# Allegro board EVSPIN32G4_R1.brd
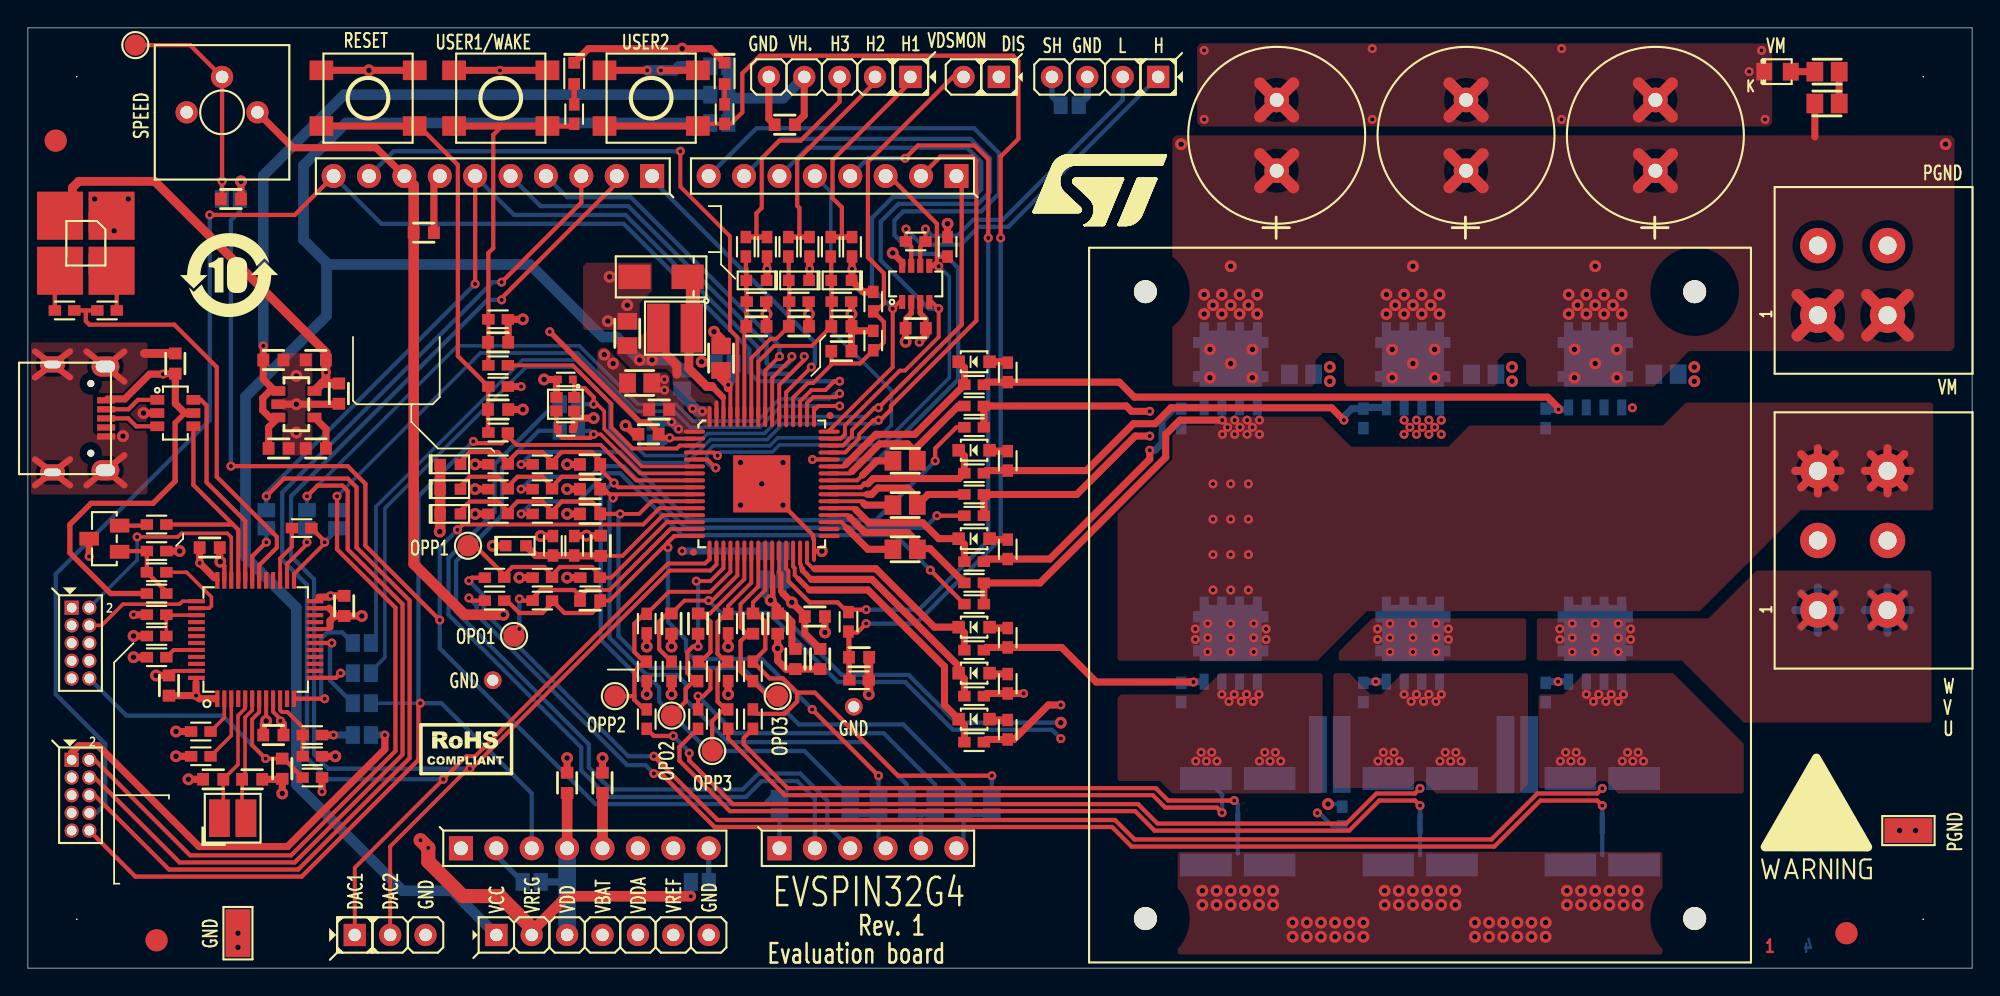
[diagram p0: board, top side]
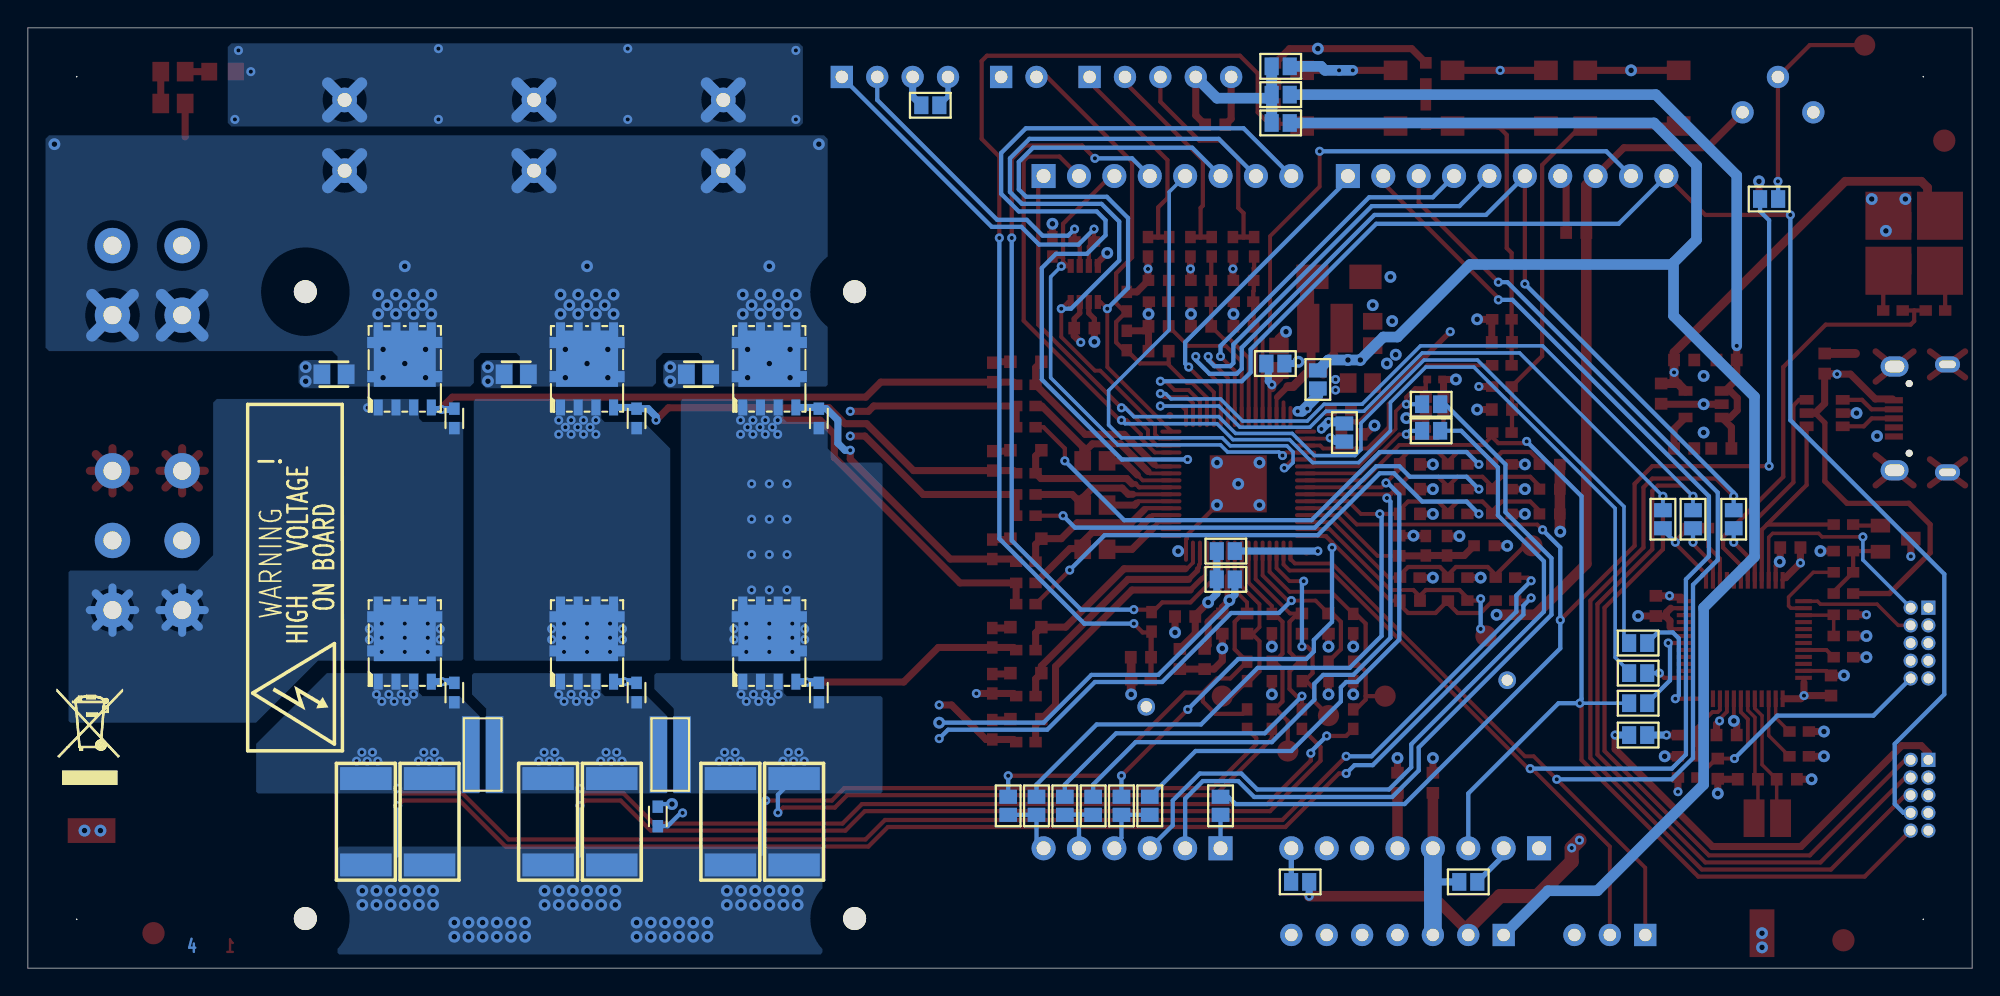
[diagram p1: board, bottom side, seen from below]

Outline 139.54 x 67.5 mm; copper layers: TOP, GND, PWR, BOTTOM. Coordinates in mm from the lower left corner of the outline.
Outline path: 0,67.5 0,0 139.54,0 139.54,67.5 0,67.5

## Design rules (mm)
constraint set DEFAULT: min track width 0.2
net group VSHUNT1: nets VSHUNT1N
net group VSHUNT2: nets VSHUNT2N
net group VSHUNT3: nets VSHUNT3N

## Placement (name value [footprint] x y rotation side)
C1  10uF  [C0805]  43.02 45.56 270 top
C2  220nF  [C0805]  49.75 43.78 270 top
C3  C-0603  [C0603]  58.39 44.29 180 top
C4  6.8pF  [C0402]  38.57 42.26 180 top
C5  6.8pF  [C0402]  38.57 38.7 180 top
C6  10uF  [C0805]  43.91 42 0 top
C7  100nF  [C0603]  45.31 40.1 180 top
C8  1uF  [C0603]  56.86 22.19 90 top
C9  100nF  [C0603]  56.48 25.24 0 top
C10  1uF  [C0603]  53.81 24.73 90 top
C11  100nF  [C0603]  55.08 22.19 270 top
C12  100nF  [C0603]  44.54 38.32 180 top
C13  220nF  [C0805]  117.57 42.64 180 bottom
C14  220nF  [C0805]  104.49 42.64 180 bottom
C15  220nF  [C0805]  91.41 42.64 180 bottom
C16  1uF  [C0805]  62.96 36.42 180 top
C17  1uF  [C0805]  62.96 33.24 180 top
C18  1uF  [C0805]  62.96 30.07 180 top
C19  33nF  [C0603]  41.11 30.32 270 top
C20  33nF  [C0603]  46.19 24.73 90 top
C21  33nF  [C0603]  14.57 55.21 180 top
C22  C-0603  [C0603]  40.35 26.38 180 top
C23  C-0603  [C0603]  48.1 24.73 270 top
C24  C-0603  [C0603]  52.04 24.73 270 top
C25  82nF  [C0603]  40.35 36.16 0 top
C26  82nF  [C0603]  40.35 34.38 0 top
C27  82nF  [C0603]  40.35 32.61 0 top
C28  100nF  [C0603]  38.7 13.3 90 top
C29  100nF  [C0603]  41.24 13.3 90 top
C30  100nF  [C0603]  28.41 52.8 0 top
C31  220uF  [D500P200]  89.63 59.78 90 top
C32  220uF  [D500P200]  103.22 59.78 90 top
C33  220uF  [D500P200]  116.81 59.78 90 top
C34  1nF  [C0603]  58.39 46.07 0 top
C35  1nF  [C0603]  55.34 46.07 0 top
C36  1nF  [C0603]  52.29 46.07 0 top
C37  100nF  [C0603]  54.32 60.55 0 top
C38  1nF  [C0603]  33.75 44.93 0 top
C39  1nF  [C0603]  59.66 22.32 0 top
C40  1nF  [C0603]  33.75 40.1 0 top
C41  100nF  [C0603]  63.72 45.94 180 top
C42  100nF  [C0603]  10.58 43.4 270 top
C43  100nF  [C0603]  20.67 43.66 0 top
C44  1uF  [C0603]  17.62 43.66 180 top
C45  100nF  [C0603]  18 37.31 180 top
C46  1uF  [C0603]  22.32 41.24 90 top
C47  10nF  [C0603]  20.67 37.31 0 top
C48  100pF  [C0603]  13.3 13.56 180 top
C49  100pF  [C0603]  16.1 13.56 0 top
C50  100nF  [C0603]  18.25 14.32 90 top
C51  100nF  [C0603]  10.13 20.29 270 top
C52  100nF  [C0603]  17.62 16.73 0 top
C53  100nF  [C0603]  22.7 26 90 top
C54  100nF  [C0603]  13.05 30.19 180 top
CN5  STRIP-P2_54-10P-FEMALE  [SIL-SOCKET10PIN-P254]  33.37 56.86 270 top
CN6  STRIP-P2_54-8P-FEMALE  [SIL-SOCKET8PIN-P254]  39.97 8.6 90 top
CN8  STRIP-P2_54-6P-FEMALE  [SIL-SOCKET6PIN-P254]  60.29 8.6 0 top
CN9  STRIP-P2_54-8P-FEMALE  [SIL-SOCKET8PIN-P254]  57.75 56.86 270 top
CON1  Power con3P  [2834082-2-TE]  130.97 30.7 90 top
CON2  Power con2P  [2834082-1-TE]  130.97 49.37 90 top
D1  STPS1H100A  [SMA]  45.45 49.62 270 top
D2  BAT60J  [SOD-323]  67.91 43.53 0 top
D3  BAT60J  [SOD-323]  67.91 37.18 0 top
D4  BAT60J  [SOD-323]  67.91 30.83 0 top
D5  BAT60J  [SOD-323]  67.91 17.87 0 top
D6  BAT60J  [SOD-323]  67.91 21.18 0 top
D7  BAT60J  [SOD-323]  67.91 24.48 0 top
D8  BAT30K  [SOD523]  35.02 30.32 0 top
D9  BAT30K  [SOD523]  30.32 36.16 0 top
D10  BAT30K  [SOD523]  30.32 34.38 0 top
D11  BAT30K  [SOD523]  30.32 32.61 0 top
D12  BAT30K  [SOD523]  58.39 49.37 180 top
D13  BAT30K  [SOD523]  55.34 49.37 180 top
D14  BAT30K  [SOD523]  52.29 49.37 180 top
J2  STRIP 1x2  [STRIP254P-M-2]  68.42 63.98 270 top
J3  STRIP 2x5  [PIN2X5P127]  3.78 12.41 0 top
J4  STRIP 1x3  [STRIP254P-M-3]  26 2.38 90 top
J5  STRIP 1x7  [STRIP254P-M-7]  41.24 2.38 90 top
J6  STRIP 1x5  [STRIP254P-M-5]  58.26 63.98 270 top
J7  STRIP 1x4  [STRIP254P-M-4]  77.31 63.98 270 top
J8  Micro USB Type B  [629105150521-USB-MICRO-B-WE]  -0.03 39.46 270 top
J9  STRIP 2x5  [PIN2X5P127]  3.78 23.34 0 top
JP1  OPEN  [JUMPER-LARGO5_5MM]  106.9 15.33 90 bottom
JP2  OPEN  [JUMPER-LARGO5_5MM]  93.44 15.33 90 bottom
L1  18uH  [7447732115-WURTH]  46.45 45.94 180 top
LED1  RED  [LED-0805]  125.57 64.36 0 top
LED2  YELLOW  [LED-0603]  39.21 64.23 270 top
LED3  YELLOW  [LED-0603]  50 64.23 270 top
LED4  RED-GREEN LED  [PLCC4]  4.16 52.04 180 top
NET1  PCB short  [CURRENTSENSE]  113 10.38 270 bottom
NET2  PCB short  [CURRENTSENSE]  99.92 10.38 270 bottom
NET3  PCB short  [CURRENTSENSE]  86.83 10.38 270 bottom
NOREF  -  [unnamed]  2 59.4 0 top
NOREF#2  -  [#2]  139.54 0 90 top
NOREF#3  -  [#2]  72.09 53.69 0 top
NOREF#4  -  [unnamed#3]  99.92 26.06 0 top
NOREF#5  -  [unnamed]  9.24 2 0 top
NOREF#6  -  [unnamed]  136.04 64 90 top
NOREF#7  -  [#2]  10.92 46.74 0 top
NOREF#8  -  [unnamed]  3.5 3.5 90 top
NOREF#9  -  [#2]  128.17 9.01 0 top
NOREF#10  -  [unnamed]  130.52 2.51 0 top
NOREF#11  -  [unnamed]  3.5 64 90 top
NOREF#12  -  [#2]  0 67.5 0 top
NOREF#13  -  [#2]  219.42 15.46 0 top
NOREF#14  -  [#2]  31.39 15.71 0 top
NOREF#15  -  [unnamed]  136.04 3.5 90 top
NOREF#16  -  [#2]  5.55 -99.73 0 top
NOREF#17  -  [#2]  134.59 43.66 0 top
NOREF#18  -  [#2]  120.13 27.84 90 bottom
NOREF#19  -  [#2]  135.14 17.46 180 bottom
NTC1  10k  [R0603]  94.33 10.89 180 bottom
Q1  STL110N10F7  [PFLAT_6X5-8LEADS]  112.49 43.02 90 bottom
Q2  STL110N10F7  [PFLAT_6X5-8LEADS]  99.41 43.02 90 bottom
Q3  STL110N10F7  [PFLAT_6X5-8LEADS]  86.33 43.02 90 bottom
Q4  STL110N10F7  [PFLAT_6X5-8LEADS]  112.49 23.34 90 bottom
Q5  STL110N10F7  [PFLAT_6X5-8LEADS]  99.41 23.34 90 bottom
Q6  STL110N10F7  [PFLAT_6X5-8LEADS]  86.33 23.34 90 bottom
Q7  BC847B  [SOT23]  5.49 30.83 90 top
R1  0  [J0805]  50 43.4 270 bottom
R2  22k  [R0603]  60.67 47.85 180 top
R3  10k  [R0603]  60.67 45.05 0 top
R6  0  [J0805]  46.96 42.26 0 bottom
R7  0  [J0805]  45.05 38.45 0 bottom
R8  0  [J0805]  53.56 29.94 90 bottom
R9  0  [J0805]  53.56 27.91 270 bottom
R10  0  [R0603]  70.32 42.77 0 top
R11  0  [R0603]  70.32 36.42 0 top
R12  0  [R0603]  70.32 30.07 0 top
R13  33  [R0603]  67.91 41.88 90 top
R14  33  [R0603]  67.91 35.53 90 top
R15  33  [R0603]  67.91 29.18 90 top
R16  R-0805  [R0603]  108.93 39.46 0 bottom
R17  R-0805  [R0603]  95.85 39.46 0 bottom
R18  R-0805  [R0603]  82.77 39.46 0 bottom
R19  0  [R0603]  67.91 40.35 90 top
R20  0  [R0603]  67.91 34 90 top
R21  0  [R0603]  67.91 27.65 90 top
R22  0  [R0603]  70.32 17.11 0 top
R23  0  [R0603]  70.32 20.41 0 top
R24  0  [R0603]  70.32 23.72 0 top
R25  33  [R0603]  67.91 16.22 90 top
R26  33  [R0603]  67.91 19.53 90 top
R27  33  [R0603]  67.91 22.83 90 top
R28  R-0805  [R0603]  108.93 19.78 0 bottom
R29  R-0805  [R0603]  95.85 19.78 0 bottom
R30  R-0805  [R0603]  82.77 19.78 0 bottom
R31  10m  [R2512]  110.71 10.51 90 bottom
R32  10m  [R2512]  115.28 10.51 90 bottom
R33  10m  [R2512]  97.63 10.51 90 bottom
R34  10m  [R2512]  102.2 10.51 90 bottom
R35  10m  [R2512]  84.55 10.51 90 bottom
R36  10m  [R2512]  89.12 10.51 90 bottom
R37  72.3k  [R0603]  37.69 30.32 180 top
R38  0  [J0805]  14.57 55.21 90 bottom
R39  3.01k  [R0603]  39.21 30.32 0 top
R40  4.7k  [R0603]  46.19 21.3 180 top
R41  22k  [R0603]  36.92 28.03 270 top
R42  22k  [R0603]  44.42 21.3 0 top
R43  22k  [R0603]  50.26 21.3 0 top
R44  1.5k  [R0603]  33.49 28.03 90 top
R45  1.5k  [R0603]  44.42 17.87 180 top
R46  1.5k  [R0603]  50.26 17.87 180 top
R47  22k  [R0603]  40.35 28.03 90 top
R48  22k  [R0603]  44.42 24.73 180 top
R49  22k  [R0603]  50.26 24.73 180 top
R50  1.5k  [R0603]  33.49 26.38 90 top
R51  1.5k  [R0603]  48.1 17.87 180 top
R52  1.5k  [R0603]  52.04 17.87 180 top
R53  11k  [R0603]  36.92 26.38 90 top
R54  11k  [R0603]  48.1 21.3 180 top
R55  11k  [R0603]  52.04 21.3 180 top
R56  68k  [R0603]  67.91 38.83 270 top
R57  27k  [R0603]  36.92 36.16 90 top
R58  68k  [R0603]  67.91 32.48 270 top
R59  27k  [R0603]  36.92 34.38 90 top
R60  68k  [R0603]  67.91 26.13 270 top
R61  27k  [R0603]  36.92 32.61 90 top
R62  3.9k  [R0603]  33.75 36.16 90 top
R63  3.9k  [R0603]  33.75 34.38 90 top
R64  3.9k  [R0603]  33.75 32.61 90 top
R65  0  [J0805]  36.16 6.19 270 bottom
R66  0  [J0805]  48.23 6.19 270 bottom
R67  0  [J0805]  53.94 11.65 0 bottom
R68  0  [J0805]  38.83 40.48 270 bottom
R69  0  [J0805]  38.83 38.58 270 bottom
R70  0  [J0805]  59.02 11.65 0 bottom
R71  0  [J0805]  63.09 11.65 0 bottom
R72  0  [J0805]  67.15 11.65 0 bottom
R73  0  [J0805]  61.05 11.65 0 bottom
R74  0  [J0805]  65.12 11.65 0 bottom
R75  0  [J0805]  69.18 11.65 0 bottom
R76  4.7k  [R0805]  129.13 62.07 0 top
R77  4.7k  [R0805]  129.13 64.36 180 top
R78  10k  [R0603]  59.15 51.78 180 top
R79  10k  [R0603]  56.1 51.78 180 top
R80  10k  [R0603]  53.05 51.78 180 top
R81  10k  [R0603]  57.62 51.78 0 top
R82  10k  [R0603]  54.58 51.78 0 top
R83  10k  [R0603]  51.53 51.78 0 top
R84  0  [J0805]  49.62 62.71 90 bottom
R85  R-0603  [R0603]  58.39 47.85 270 top
R86  R-0603  [R0603]  55.34 47.85 270 top
R87  0  [J0805]  49.62 60.67 90 bottom
R88  R-0603  [R0603]  52.29 47.85 270 top
R89  0  [J0805]  49.62 64.74 90 bottom
R90  100k  [R0603]  33.75 41.75 90 top
R91  200  [R0603]  33.75 43.27 90 top
R92  200  [R0603]  33.75 38.45 90 top
R93  100k  [R0603]  33.75 46.58 90 top
R94  120  [R0603]  39.21 61.31 180 top
R95  120  [R0603]  50 61.31 180 top
R96  200  [R0603]  58.89 24.86 180 top
R97  100k  [R0603]  59.66 20.67 90 top
R98  120  [R0603]  63.72 52.16 270 top
R99  10k  [R0603]  66.01 51.78 0 top
R100  0  [J0805]  74.77 61.94 90 bottom
R101  10k  [R0603]  9.24 26.89 270 top
R102  100  [R0603]  9.24 28.42 90 top
R103  36k  [R0603]  9.24 29.94 270 top
R104  1.5k  [R0603]  9.24 31.84 270 top
R105  4.7k  [R0603]  20.41 16.73 90 top
R106  4.7k  [R0603]  20.41 15.21 270 top
R107  4.7k  [R0603]  9.24 23.84 90 top
R108  0  [J0805]  23.97 16.73 90 bottom
R109  0  [J0805]  23.97 23.34 90 bottom
R110  2.7k  [R0603]  9.24 25.37 270 top
R111  0  [J0805]  23.97 21.18 90 bottom
R112  0  [J0805]  20.03 32.23 180 bottom
R113  0  [J0805]  22.19 32.23 180 bottom
R114  100  [R0603]  19.65 31.59 90 top
R115  0  [J0805]  17.11 32.23 180 bottom
R116  10k  [R0603]  12.41 16.99 270 top
R117  R-0603  [R0603]  12.41 15.21 270 top
R118  0  [J0805]  23.97 19.02 90 bottom
R119  100k  [R0603]  9.24 22.32 90 top
R120  100k  [R0603]  20.41 13.68 90 top
R121  100  [R0603]  2.63 47.21 270 top
R122  100  [R0603]  5.68 47.21 90 top
SW1  6x6 J-bend SMT  [BUTTON_L6_2_W6_2]  33.94 62.45 180 top
SW2  6x6 J-bend SMT  [BUTTON_L6_2_W6_2]  44.73 62.45 180 top
SW3  6x6 J-bend SMT  [BUTTON_L6_2_W6_2]  24.41 62.45 180 top
TP1  TP-SMD-S1751-46R  [TP_SMD_135_70]  134.97 9.87 0 top
TP2  TP-SMD-S1751-46R  [TP_SMD_135_70]  15.08 2.51 90 top
TP3  TP-SMD-diam1_5mm  [TP-D60]  7.71 66.26 90 top
TP4  TP-SMD-diam1_5mm  [TP-D60]  31.59 30.32 270 top
TP5  TP-SMD-diam1_5mm  [TP-D60]  42.13 19.53 270 top
TP6  TP-SMD-diam1_5mm  [TP-D60]  49.12 15.59 270 top
TP7  TP-SMD-diam1_5mm  [TP-D60]  34.89 23.84 270 top
TP8  TP-SMD-diam1_5mm  [TP-D60]  46.19 18.13 90 top
TP9  TP-SMD-diam1_5mm  [TP-D60]  53.81 19.53 90 top
TP10  TP-diam1_27mm-Hole0_8mm  [TP-SONDA]  59.28 18.76 0 top
TP11  TP-diam1_27mm-Hole0_8mm  [TP-SONDA]  33.37 20.67 0 top
TR1  100k  [TRIMMER-3386P-BOURNS]  13.94 61.44 0 top
U1  STSPIN32G4  [VFQFPN9X9X1_0-64L-EXP]  52.67 34.77 0 top
U2  TCAN330DCNT  [SOT23-8L]  63.72 49.12 0 top
U3  LD3985M33R  [SOT23-5L]  19.27 40.48 270 top
U4  USBLC6-2SC6  [SOT23-6L]  10.58 39.85 270 top
U5  STM32F103CBT6  [LQFP48_L7_W7_P0_5]  16.35 23.59 90 top
X1  24.000MHZ  [ABMM11W]  38.57 40.48 180 top
X2  NX3225CD-CRYSTAL  [XTAL_L3_2_W2_5_2PINS]  14.7 10.76 0 top

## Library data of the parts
C1 C2 C6 C13-C18 = C-0805
C3 C7-C12 C19-C30 C34-C54 = C-0603
C4 C5 = C-0402
C31-C33 = CAP POL: Tolerance: TOL; User Part Number: PART#
CN5 = STRIP-P2_54-10P-FEMALE
CN6 CN9 = STRIP-P2_54-8P-FEMALE
CN8 = STRIP-P2_54-6P-FEMALE
CON1 = TE_con3P_20A_p5mm
CON2 = TE_con2P_20A_p5mm
D1 = STPS1H100A
D2-D7 = BAT60J
D8-D14 = BAT30K
J2 = STRIP 1x2
J3 J9 = STRIP 2x5
J4 = STRIP 1x3
J5 = STRIP 1x7
J6 = STRIP 1x5
J7 = STRIP 1x4
J8 = USB-microB-629105150521-WE-SMT
JP1 JP2 = Jumper a Goccia-Largo 5_5mm
L1 = INDUCTOR-7447732115-WE
LED1 = LED-0805-RED-WE
LED2 LED3 = LED-0603-YELLOW-WE
LED4 = HSMF-A201-A00J1
NET1-NET3 = CurrentSense
NTC1 = NTC-NCP18XH103F03RB
Q1-Q6 = STLD110N10F7
Q7 = BC847B
R1-R3 R6-R9 R37-R122 = R-0603
R10-R30 = R-0805
R31-R36 = R-2512
SW1-SW3 = 430483025816
TP1 TP2 = TP-SMD-S2761-46R
TP3-TP9 = TP-SMD-diam1_5mm
TP10 TP11 = TP-diam1_27mm-Hole0_8mm
TR1 = TRIMMER 3386P
U1 = STSPIN32G4
U2 = TCAN330DCNT
U3 = LD3985M33R
U4 = USBLC6-2SC6
U5 = STM32F103CBT6
X1 = CRYSTAL-ABM11W
X2 = NX3225CD-CRYSTAL

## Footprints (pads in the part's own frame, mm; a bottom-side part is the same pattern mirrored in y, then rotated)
2834082-1-TE
  round 2.54 hole 1.3: 1(-2.5,2.5) 2(-2.5,-2.5) 3(2.5,2.5) 4(2.5,-2.5)
2834082-2-TE
  round 2.54 hole 1.3: 1(-5,2.5) 2(-5,-2.5) 3(0,2.5) 4(0,-2.5) 5(5,2.5) 6(5,-2.5)
7447732115-WURTH
  rect 1.6x3.5 smd: 1(-1.2,0) 2(1.2,0)
629105150521-USB-MICRO-B-WE
  round 0.508 hole 0.8 unplated: (-2.5,4.55) (2.5,4.55)
  rect 0.45x1.3 smd: 1(-1.3,5.65) 2(-0.65,5.65) 3(0,5.65) 4(0.65,5.65) 5(1.3,5.65)
  oval 1.45x2 hole 0.85x1.4: SH1(-3.725,5.6) SH2(3.725,5.6)
  oval 1.15x1.8 hole 0.55x1.2: SH3(-3.875,1.8) SH4(3.875,1.8)
ABMM11W
  rect 0.875x0.775 smd: 1(-0.638,-0.487) 2(0.638,-0.487) 3(0.638,0.487) 4(-0.638,0.487)
BUTTON_L6_2_W6_2
  rect 1.7x1.4 smd: 1(-3.35,1.999) 2(3.35,1.999) 3(-3.35,-1.999) 4(3.35,-1.999)
C0402
  rect 0.559x0.559 smd: 1(-0.533,0) 2(0.533,0)
C0603
  rect 0.85x0.9 smd: 1(-0.725,0) 2(0.725,0)
C0805
  rect 1.2x1.4 smd: 1(-0.875,0) 2(0.875,0)
CURRENTSENSE
  rect 0.762x0.381 smd: 1(-0.356,0) 2(0.356,0)
D500P200
  round 1.778 hole 1: 1(-2.54,0) 2(2.54,0)
J0805
  rect 1.27x1.016 smd: 1(0,0.648) 2(0,-0.648)
JUMPER-LARGO5_5MM
  rect 5.5x1.27 smd: 1(0,0.851) 2(0,-0.851)
LED-0603
  rect 0.838x0.838 smd: 1(-0.762,0) 2(0.762,0)
LED-0805
  rect 1.143x1.27 smd: 1(-0.953,0) 2(0.953,0)
LQFP48_L7_W7_P0_5
  rect 1.2x0.3 smd: 1(-4.25,2.75) 2(-4.25,2.25) 3(-4.25,1.75) 4(-4.25,1.25) 5(-4.25,0.75) 6(-4.25,0.25) 7(-4.25,-0.25) 8(-4.25,-0.75) 9(-4.25,-1.25) 10(-4.25,-1.75) 11(-4.25,-2.25) 12(-4.25,-2.75) 25(4.25,-2.75) 26(4.25,-2.25) 27(4.25,-1.75) 28(4.25,-1.25) 29(4.25,-0.75) 30(4.25,-0.25) 31(4.25,0.25) 32(4.25,0.75) 33(4.25,1.25) 34(4.25,1.75) 35(4.25,2.25) 36(4.25,2.75)
  rect 0.3x1.2 smd: 13(-2.75,-4.25) 14(-2.25,-4.25) 15(-1.75,-4.25) 16(-1.25,-4.25) 17(-0.75,-4.25) 18(-0.25,-4.25) 19(0.25,-4.25) 20(0.75,-4.25) 21(1.25,-4.25) 22(1.75,-4.25) 23(2.25,-4.25) 24(2.75,-4.25) 37(2.75,4.25) 38(2.25,4.25) 39(1.75,4.25) 40(1.25,4.25) 41(0.75,4.25) 42(0.25,4.25) 43(-0.25,4.25) 44(-0.75,4.25) 45(-1.25,4.25) 46(-1.75,4.25) 47(-2.25,4.25) 48(-2.75,4.25)
PFLAT_6X5-8LEADS
  rect 1.143x0.65 smd: 1(-2.771,1.905) 2(-2.771,0.635) 3(-2.771,-0.635) 4(-2.771,-1.905) 5(2.771,-1.905) 6(2.771,-0.635) 7(2.771,0.635) 8(2.771,1.905)
PIN2X5P127
  rect 1.016x1.016 hole 0.7: 1(-0.635,2.54)
  round 1.016 hole 0.7: 2(0.635,2.54) 3(-0.635,1.27) 4(0.635,1.27) 5(-0.635,0) 6(0.635,0) 7(-0.635,-1.27) 8(0.635,-1.27) 9(-0.635,-2.54) 10(0.635,-2.54)
PLCC4
  rect 1.1x1.5 smd: A1(-0.75,1.5) A2(0.75,-1.5) K1(-0.75,-1.5) K2(0.75,1.5)
R0603
  rect 0.762x0.889 smd: 1(0,0.699) 2(0,-0.699)
R0805
  rect 1.2x1.4 smd: 1(-0.875,0) 2(0.875,0)
R2512
  rect 1.65x3.7 smd: 1(-3.1,0) 2(3.1,0)
SIL-SOCKET6PIN-P254
  rect 1.727x1.727 hole 1: 1(-6.35,0)
  round 1.727 hole 1: 2(-3.81,0) 3(-1.27,0) 4(1.27,0) 5(3.81,0) 6(6.35,0)
SIL-SOCKET8PIN-P254
  rect 1.727x1.727 hole 1: 1(0,8.89)
  round 1.727 hole 1: 2(0,6.35) 3(0,3.81) 4(0,1.27) 5(0,-1.27) 6(0,-3.81) 7(0,-6.35) 8(0,-8.89)
SIL-SOCKET10PIN-P254
  rect 1.727x1.727 hole 1: 1(0,11.43)
  round 1.727 hole 1: 2(0,8.89) 3(0,6.35) 4(0,3.81) 5(0,1.27) 6(0,-1.27) 7(0,-3.81) 8(0,-6.35) 9(0,-8.89) 10(0,-11.43)
SMA
  rect 1.753x2.311 smd: 1(0,1.905) 2(0,-1.905)
SOD523
  rect 0.838x0.8 smd: 1(-0.731,0) 2(0.731,0)
SOD-323
  rect 0.9x0.9 smd: 1(-1.11,0) 2(1.11,0)
SOT23
  rect 0.991x1.397 smd: 1(-0.94,-1.092) 2(0.94,-1.092) 3(0,1.092)
SOT23-5L
  rect 0.69x1 smd: 1(-0.95,-1.295) 2(0,-1.295) 3(0.95,-1.295) 4(0.95,1.295) 5(-0.95,1.295)
SOT23-6L
  rect 0.69x1 smd: 1(-0.95,-1.295) 2(0,-1.295) 3(0.95,-1.295) 4(0.95,1.295) 5(0,1.295) 6(-0.95,1.295)
SOT23-8L
  rect 0.45x1 smd: 1(-0.975,-1.295) 2(-0.325,-1.295) 3(0.325,-1.295) 4(0.975,-1.295) 5(0.975,1.295) 6(0.325,1.295) 7(-0.325,1.295) 8(-0.975,1.295)
STRIP254P-M-2
  rect 1.6x1.6 hole 0.9: 1(0,1.27)
  round 1.6 hole 0.9: 2(0,-1.27)
STRIP254P-M-3
  rect 1.6x1.6 hole 0.9: 1(0,2.54)
  round 1.6 hole 0.9: 2(0,0) 3(0,-2.54)
STRIP254P-M-4
  rect 1.6x1.6 hole 0.9: 1(0,3.81)
  round 1.6 hole 0.9: 2(0,1.27) 3(0,-1.27) 4(0,-3.81)
STRIP254P-M-5
  rect 1.6x1.6 hole 0.9: 1(0,5.08)
  round 1.6 hole 0.9: 2(0,2.54) 3(0,0) 4(0,-2.54) 5(0,-5.08)
STRIP254P-M-7
  rect 1.6x1.6 hole 0.9: 1(0,7.62)
  round 1.6 hole 0.9: 2(0,5.08) 3(0,2.54) 4(0,0) 5(0,-2.54) 6(0,-5.08) 7(0,-7.62)
TP-D60
  round 1.524 smd: 1(0,0)
TP-SONDA
  round 1.27 hole 0.8: 1(0,0)
TP_SMD_135_70
  rect 3.429x1.778 smd: 1(0,0)
TRIMMER-3386P-BOURNS
  round 1.6 hole 0.9: 1(2.54,0) 2(0,2.54) 3(-2.54,0)
unnamed
  round 1.6 smd: (0,0)
unnamed#3
  round 1.651 hole 3.2 unplated: (-19.71,22.5) (-19.71,-22.5) (19.71,22.5) (19.71,-22.5)
VFQFPN9X9X1_0-64L-EXP
  round 0.508 smd: (-4.902,-4.902) (4.902,4.902)
  oval 1.524x0.29 smd: 1(-4.832,3.749) 2(-4.832,3.249) 3(-4.832,2.749) 4(-4.832,2.249) 5(-4.832,1.75) 6(-4.832,1.25) 7(-4.832,0.75) 8(-4.832,0.25) 9(-4.832,-0.25) 10(-4.832,-0.75) 11(-4.832,-1.25) 12(-4.832,-1.75) 13(-4.832,-2.249) 14(-4.832,-2.749) 15(-4.832,-3.249) 16(-4.832,-3.749) 33(4.832,-3.749) 34(4.832,-3.249) 35(4.832,-2.749) 36(4.832,-2.249) 37(4.832,-1.75) 38(4.832,-1.25) 39(4.832,-0.75) 40(4.832,-0.25) 41(4.832,0.25) 42(4.832,0.75) 43(4.832,1.25) 44(4.832,1.75) 45(4.832,2.249) 46(4.832,2.749) 47(4.832,3.249) 48(4.832,3.749)
  oval 0.29x1.524 smd: 17(-3.749,-4.832) 18(-3.249,-4.832) 19(-2.749,-4.832) 20(-2.249,-4.832) 21(-1.75,-4.832) 22(-1.25,-4.832) 23(-0.75,-4.832) 24(-0.25,-4.832) 25(0.25,-4.832) 26(0.75,-4.832) 27(1.25,-4.832) 28(1.75,-4.832) 29(2.249,-4.832) 30(2.749,-4.832) 31(3.249,-4.832) 32(3.749,-4.832) 49(3.749,4.832) 50(3.249,4.832) 51(2.749,4.832) 52(2.249,4.832) 53(1.75,4.832) 54(1.25,4.832) 55(0.75,4.832) 56(0.25,4.832) 57(-0.25,4.832) 58(-0.75,4.832) 59(-1.25,4.832) 60(-1.75,4.832) 61(-2.249,4.832) 62(-2.749,4.832) 63(-3.249,4.832) 64(-3.749,4.832)
  rect 4.1x4.1 smd: 65(0,0)
XTAL_L3_2_W2_5_2PINS
  rect 1.5x2.7 smd: 1(-0.95,0) 2(0.95,0)

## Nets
3V3_STLINK: C43.2 C46.2 C51.2 C52.2 C53.2 C54.2 J9.1 LED4.A2 Q7.3 R110.2 R120.2 U3.5 U5.1 U5.9 U5.24 U5.36 U5.48
5V: C29.1 C42.2 C44.2 C45.2 CN6.5 J8.1 R84.2 R101.2 U3.1(VIN) U3.3 U4.5(VBUS)
GND: C1.1 C2.1 C3.1 C4.2 C5.1 C6.1 C7.2 C8.1 C9.2 C10.1 C11.2 C12.2 C13.1 C14.1 C15.1 C19.1 C20.1 C21.1 C25.1 C26.1 C27.1 C28.2 C29.2 C30.2 C31.2 C32.2 C33.2 C34.2 C35.2 C36.2 C37.1 C38.2 C39.2 C40.2 C41.2 C42.1 C43.1 C44.1 C45.1 C46.1 C47.1 C48.2 C49.2 C50.1 C51.1 C52.1 C53.1 C54.1 CN5.7 CN6.6 CN6.7 CON2.3 CON2.4 D1.2 J3.3 J3.5 J3.9 J4.3 J5.7 J6.5 J7.3 J8.5 J8.SH1 J8.SH2 J8.SH3 J8.SH4(SHIELD#SH4) J9.3 J9.5 J9.9 LED1.1 LED2.1 LED3.1 LED4.K1 NET1.2 NET2.2 NET3.2 R3.1 R31.1 R32.1 R33.1 R34.1 R35.1 R36.1 R39.1 R40.1 R47.1 R48.1 R49.1 R62.1 R63.1 R64.1 R85.1 R86.1 R88.1 R93.2 R97.2 R99.1 R100.1 R103.1 R106.1 R107.1 R116.2 R117.2 R119.1 SW3.3 SW3.4 TP1.1 TP2.1 TP10.1 TP11.1 TR1.3 U1.32 U1.65(VSS) U2.2 U2.8 U3.2 U4.2 U5.8 U5.20 U5.23 U5.35 U5.47(VSS_3) X1.2 X1.4(GND#4)
VBAT: C12.1 J5.4 R7.1 U1.2
VCC: C1.2 J5.1 L1.2 R6.2 R87.2 U1.63
VDD: C6.2 C7.1 C28.1 C41.1 CN6.4 D12.1(C) D13.1(C) D14.1(C) J2.1 J3.1 J5.3 R2.2 R7.2 R8.2 R65.2 R78.1 R79.1 R80.1 R89.2 R90.2 R108.1 SW1.3 SW1.4 SW2.3 SW2.4 U1.1 U2.3(VCC)
VDDA: C8.2 C9.1 D8.1(C) D9.1(C) D10.1(C) D11.1(C) J5.5 R8.1 R9.2 U1.27
BOOT1: C16.2 U1.41
BOOT2: C17.2 U1.38
BOOT3: C18.2 U1.35
F103_NRST: C50.2 J9.10 R120.1 U5.7
F103_SWCLK: J9.4 U5.37
F103_SWDIO: J9.2 U5.34
GHS1: D2.1(C) R13.1 U1.43
GHS2: D3.1(C) R14.1 U1.40
GHS3: D4.1(C) R15.1 U1.37
GLS1: D5.1(C) R25.1 U1.29
GLS2: D6.1(C) R26.1 U1.30
GLS3: D7.1(C) R27.1 U1.31
OUT1: C16.1 R19.1 U1.42
OUT2: C17.1 R20.1 U1.39
OUT3: C18.1 R21.1 U1.36
PA0: C19.2 D8.2 R37.1 R39.2 U1.13
PA1: R41.1 R44.2 R47.2 TP4.1 U1.14
PA2: C22.2 R53.1 TP7.1 U1.15
PA3: C22.1 R50.2 R53.2 R73.2 U1.16
PA4: CN5.3 J4.1 U1.17
PA5: CN5.2 J4.2 U1.18
PA6: C23.2 R54.1 TP8.1 U1.19
PA7: R42.1 R45.2 R48.2 TP5.1 U1.20
PA8: CN9.8 U1.44
PA9: CN9.2 R111.1 U1.45
PA10: CN9.1 R109.1 U1.46
PA11: CN9.7 U1.47 U2.4
PA12: CN9.6 U1.48 U2.1
PA13: J3.2 R113.1 U1.49
PA14: J3.4 R112.1 U1.50
PA15: CN5.10 J3.8 U1.51
PB0: R43.1 R46.2 R49.2 TP6.1 U1.23
PB1: C24.2 R55.1 TP9.1 U1.24
PB2: C24.1 R52.2 R55.2 R75.2 U1.25
PB3: CN5.6 J3.6 R115.1 U1.54
PB4: CN5.5 U1.55
PB5: CN5.4 U1.56
PB6: C34.1 D12.2 R81.2 R85.2 U1.57
PB7: C35.1 D13.2 R82.2 R86.2 U1.58
PB8: C36.1 D14.2 R83.2 R88.2 U1.59
PB9: CN5.9 U1.60
PB10: CN9.4 R96.2 U1.28
PC0: C25.2 D9.2 R57.2 R62.2 R70.2 U1.9
PC1: C26.2 D10.2 R59.2 R63.2 R71.2 U1.10
PC2: C27.2 D11.2 R61.2 R64.2 R72.2 U1.11
PC3: R38.1 R67.2 U1.12
PC4: C20.2 NTC1.2 R40.2 U1.21
PC5: C23.1 R51.2 R54.2 R74.2 U1.22
PC13: R91.2 U1.3
PC14: CN9.3 R99.2 U1.4 U2.5
PC15: CN9.5 U1.5
PD2: CN5.1 U1.53
PF0: C4.1 R68.2 U1.6 X1.1
PF1: C5.2 R69.2 U1.7 X1.3
PG10: CN6.3 J3.10 R92.2 R118.1 U1.8
SCREF: C3.2 J2.2 R2.1 R3.2 U1.52
STLINK_LED: R121.1 R122.1 U5.30
STLINK_NRST: R118.2 U5.18
STLINK_SWCLK: R112.2 U5.26
STLINK_SWDIO: R113.2 R114.2 U5.25
STLINK_SWO: R115.2 U5.31
STLINK_UART_RX: R111.2 U5.13
STLINK_UART_TX: R109.2 U5.12
SW: D1.1 L1.1 U1.62
U: CON1.1 CON1.2 Q1.1 Q1.2 Q1.3(S#3) Q4.5 Q4.6 Q4.7 Q4.8 R16.1 R19.2 R56.1
USB_DM: U4.6 U5.32
USB_DP: R104.1 U4.4 U5.33
USB_RENUM: R102.2 U5.38
V: CON1.3 CON1.4 Q2.1 Q2.2 Q2.3(S#3) Q5.5 Q5.6 Q5.7 Q5.8 R17.1 R20.2 R58.1
VHALL: C37.2 J6.4 R84.1 R87.1 R89.1
VM: C13.2 C14.2 C15.2 C31.1 C32.1 C33.1 CON2.1 CON2.2 Q1.5 Q1.6 Q1.7 Q1.8 Q2.5 Q2.6 Q2.7 Q2.8 Q3.5 Q3.6 Q3.7 Q3.8 R1.1 R37.2 R76.1
VREF+: C10.2 C11.1 C30.1 CN5.8 J5.6 NTC1.1 R9.1 R41.2 R42.2 R43.2 TR1.1 U1.26
VREGIN: J5.2 R6.1 R66.1 U1.64
VSHUNT1N: NET1.1 R50.1
VSHUNT1P: JP1.1 Q4.1 Q4.2 Q4.3(S#3) R28.1 R31.2 R32.2 R44.1
VSHUNT2N: NET2.1 R51.1
VSHUNT2P: JP1.2 JP2.1 Q5.1 Q5.2 Q5.3(S#3) R29.1 R33.2 R34.2 R45.1
VSHUNT3N: NET3.1 R52.1
VSHUNT3P: JP2.2 Q6.1 Q6.2 Q6.3(S#3) R30.1 R35.2 R36.2 R46.1
W: CON1.5 CON1.6 Q3.1 Q3.2 Q3.3(S#3) Q6.5 Q6.6 Q6.7 Q6.8 R18.1 R21.2 R60.1
N170257: D5.2 R22.1
N170269: Q4.4 R22.2 R25.2 R28.2
N170415: Q1.4 R10.2 R13.2 R16.2
N170423: D2.2 R10.1
N174120: Q5.4 R23.2 R26.2 R29.2
N174124: D6.2 R23.1
N174270: Q2.4 R11.2 R14.2 R17.2
N174282: D3.2 R11.1
N174784: Q6.4 R24.2 R27.2 R30.2
N174788: D7.2 R24.1
N174934: Q3.4 R12.2 R15.2 R18.2
N174946: D4.2 R12.1
N180167: R116.1 U5.2
N180187: R117.1 U5.3
N180745: R105.1 R106.2 U5.10
N180799: R114.1 U5.27
N180929: J8.3 U4.3
N180941: J8.2 U4.1
N181071: Q7.2(E) R104.2
N181167: Q7.1 R101.1 R102.1 R103.2
N181233: R107.2 R110.1 U5.39
N181269: C47.2 U3.4
N181591: LED4.K2 R121.2
N181595: LED4.A1 R122.2
N181645: C48.1 U5.5 X2.1
N181657: C49.1 U5.6 X2.2
N181761: R119.2 U5.44
N258505: J6.1 R78.2 R81.1
N258509: J6.2 R79.2 R82.1
N258513: J6.3 R80.2 R83.1
N261648: C40.1 R90.1 R92.1 SW3.1 SW3.2
N262399: C39.1 R95.1 R96.1 R97.1 SW2.1 SW2.2
N265543: R76.2 R77.1
N265547: LED1.2 R77.2
N274832: CN6.2 R65.1
N274924: CN6.8 R66.2
N274964: CN8.4 R70.1 R73.1
N274968: CN8.5 R71.1 R74.1
N274972: CN8.6 R72.1 R75.1
N520147: LED3.2 R95.2
N538821: CN8.1 R67.1
N539050: CN8.3 R69.1
N539062: CN8.2 R68.1
N683197: C38.1 R91.1 R93.1 R94.1 SW1.1 SW1.2
N683205: LED2.2 R94.2
N684002: C21.2 R38.2 TP3.1 TR1.2
N685395: J7.1 R98.2 U2.7
N685399: J7.2 R98.1 U2.6
N685471: J7.4 R100.2
N728166: R58.2 R59.1
N728550: R60.2 R61.1
N729020: R56.2 R57.1
N741558: R105.2 R108.2
N741774: C2.2 R1.2 U1.61

Pads without a net: CN6 1; J3 7; J8 4; J9 6 7 8; U1 33 34; U5 4 11 14 15 16 17 19 21 22 28 29 40 41 42 43 45 46

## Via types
v1: diameter 0.65, hole 0.3, TOP to BOTTOM, 258 vias
v2: diameter 0.85, hole 0.4, TOP to BOTTOM, 200 vias

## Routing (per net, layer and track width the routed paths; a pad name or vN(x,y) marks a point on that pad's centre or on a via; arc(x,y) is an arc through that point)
3V3_STLINK: length 46.7
  TOP w0.279: U5.48 12.07,20.81 12.07,20.5 ; U5.9 17.6,18.4 18.13,17.87 v1(18.13,17.75) ; 13.49,19.34 U5.1 ; U5.24 20.9,26.64
  TOP w0.305: 13.43,28.03 13.6,27.86 U5.36
  TOP w0.508: 12.07,20.5 v1(12.07,19.56) ; v1(12.07,19.56) C51.2 ; v1(12.07,19.56) 12.29,19.34 13.49,19.34 ; R120.2 v1(21.11,12.67) ; C52.2 18.34,17.53 v1(18.13,17.75) ; R110.2 v1(7.59,25.37) ; Q7.3 v1(4.4,29.56) ; 13.43,28.03 13.38,28.03 v1(12.32,29.09) C54.2 ; C53.2 v1(21.72,26.73) 21.63,26.64 20.9,26.64
  TOP w0.635: 21.1,41.97 C46.2 ; 21.1,41.97 21.39,42.26 v1(21.39,42.77) C43.2 21.39,44.2 9.11,56.48 3.65,56.48 3.2,56.03 3.2,55.54 ; 21.1,41.97 U3.5
  PWR w0.454: 2.48,26.54 J9.1
  PWR w0.508: J9.1 3.14,27.15
5V: length 162.3
  TOP w0.381: 11.27,39.85 10.57,39.15 10.57,34.96 8.98,33.37 4.54,33.37 3.01,31.84 3.01,29.81 5.94,26.89 R101.2 ; J8.1 5.71,40.86
  TOP w0.508: U3.1 17.74,41.43 ; 17.74,41.43 17.37,41.43 16.86,40.92 16.86,40.04 17.37,39.53 U3.3 17.28,38.83 C45.2 ; 17.74,41.43 16.9,42.28 C44.2 v1(16.9,44.67) ; 5.71,40.86 6.95,40.86 8.73,42.64 v1(9.7,42.64) 9.73,42.68 C42.2 10.58,40.53 11.27,39.85 U4.5
  TOP w0.762: C29.1 CN6.5
  PWR w1.016: CN6.5 41.24,7.46 39.97,6.19 29.3,6.19 23.27,12.22 23.27,19.21 25.24,21.18 25.24,41.12 21.68,44.67 v1(16.9,44.67) 11.73,44.67 v1(9.7,42.64)
  BOTTOM w0.762: 48.99,62.71 R84.2 22.7,62.71 16.9,56.9 v1(16.9,44.67)
GND: length 366.7
  TOP w0.279: U5.47 10.45,21.34 C51.1 ; 56.42,30.79 U1.32 v2(56.98,29.93) ; 21.68,24.48 21.55,24.34 U5.20 ; U5.8 v2(17.1,17.75)
  TOP w0.305: v2(52.67,34.77) v2(54.2,33.24) 56.35,31.08 56.35,30.85 56.42,30.79 ; U5.35 14.1,28.89 v2(13.81,29.18) ; U5.23 21.63,25.84
  TOP w0.381: U2.2 63.4,47.01 63,46.61 C41.2
  TOP w0.454: J8.SH3 3.02,42.41 ; J8.SH3 0.51,42.41 ; J8.SH3 0.51,44.27 ; J8.SH3 3.02,44.27 ; 0.51,34.66 J8.SH4 ; J8.SH4 3.02,34.66 ; J8.SH4 3.02,36.52 ; J8.SH4 0.51,36.52 ; J8.SH2 6.92,36.82 ; J8.SH2 6.92,34.66 ; J8.SH2 4.21,34.66 ; J8.SH1 6.92,42.11 ; J8.SH1 6.92,44.27 ; J8.SH1 4.21,44.27
  TOP w0.457: v2(62.07,51.34) 62.75,50.66 U2.8
  TOP w0.508: 22.03,25.28 C53.1 v2(23.97,25.28) ; 22.03,25.28 21.68,24.93 21.68,24.48 ; 22.03,25.28 21.94,25.37 21.94,25.54 21.63,25.84 ; R117.2 v2(10.63,15.21) ; C35.2 v2(56.06,46.96) 56.06,47.69 56.04,47.72 R86.1 ; R107.1 v2(7.59,23.84) ; R47.1 v2(38.7,28.03) ; R49.1 v2(50.26,23.08) ; X1.4 39.21,39.46 ; 39.21,39.46 39.21,38.81 C5.1 ; 39.21,39.46 39.23,39.49 v2(40.61,39.49) ; C52.1 16.9,17.54 v2(17.1,17.75) ; R88.1 52.99,47.72 53.02,47.69 v2(53.02,46.96) C36.2 ; U4.2 v2(8.3,39.85) ; LED2.1 40.23,66.01 v2(46.96,66.01) 48.99,66.01 LED3.1 ; C41.2 v2(63,44.96) ; v2(37.05,42.26) C4.2 37.94,42.15 X1.2 ; R62.1 v2(32.1,36.16) ; R48.1 v2(44.42,23.08) ; R63.1 v2(32.1,34.38) ; C20.1 v2(46.19,23.08) ; 60.29,20.73 R97.2 ; C40.2 v2(35.53,40.1) ; C34.2 v2(59.11,46.96) 59.11,47.69 59.09,47.72 R85.1 ; C34.2 59.43,45.75 R3.1 ; C34.2 C3.1 ; R116.2 v2(10.63,16.99) ; v2(42.89,38.96) 43.53,38.32 C12.2 ; C37.1 53.18,60.97 J6.5 ; C19.1 v2(40.1,31.05) 39.24,31.05 R39.1 ; C21.1 v2(15.3,56.48) ; R103.1 v2(10.89,29.94) ; v2(18.25,12.54) C50.1 18.22,13.56 C49.2 ; C46.1 22.28,40.48 v2(19.27,40.48) U3.2 ; CN5.7 29.14,56.44 C30.2 ; C38.2 34.47,46.55 R93.2 v2(35.53,46.58) ; v2(13.81,29.18) 13.77,29.22 C54.1 ; R64.1 v2(32.1,32.61) ; R119.1 v2(7.59,22.32) ; C26.1 v2(38.7,34.38) ; C9.2 v2(57.21,24.1) ; SW3.3 v2(24.48,64.45) SW3.4 ; C27.1 v2(38.7,32.61) ; C29.2 v2(41.24,15.08) ; R106.1 v2(22.06,15.21) ; C28.2 v2(38.7,15.08) ; C51.1 v2(9.2,21.01) ; R40.1 v2(46.19,19.65) ; C8.1 C11.2 54.41,21.47 53.81,22.07 v2(53.81,22.95) C10.1 ; C48.2 v2(11.52,13.56) ; C25.1 v2(38.7,36.16) ; R99.1 v2(66.01,53.43)
  TOP w0.635: v2(60.36,19.65) R97.2 60.36,22.29 C39.2 ; C2.1 49.75,45.18 v2(49.24,45.69) ; 8.37,44.13 C42.1
  TOP w0.835: C32.2 104.42,61.12 ; C32.2 102.02,63.53 ; C32.2 102.02,61.12 ; C32.2 104.42,63.53 ; C33.2 118.01,61.12 ; C33.2 115.61,63.53 ; C33.2 115.61,61.12 ; C33.2 118.01,63.53 ; 88.43,63.53 C31.2 ; C31.2 90.83,61.12 ; C31.2 90.83,63.53 ; C31.2 88.43,61.12
  GND w0.581: 48.86,2.38 49.79,3.31 ; 48.86,2.38 47.93,1.45 ; 48.86,2.38 49.79,1.45 ; 48.86,2.38 47.93,3.31 ; 32.53,21.51 TP11.1 ; TP11.1 34.21,19.83 ; TP11.1 34.21,21.51 ; TP11.1 32.53,19.83 ; 10.44,60.48 TR1.3 ; TR1.3 10.44,62.39 ; TR1.3 12.36,60.48 ; TR1.3 12.36,62.39 ; 101.84,60.94 C32.2 ; C32.2 101.84,63.71 ; C32.2 103.22,60.44 ; C32.2 103.22,64.21 ; C32.2 104.6,63.71 ; C32.2 104.6,60.94 ; C32.2 105.1,62.32 ; C32.2 101.34,62.32 ; 45.32,9.61 CN6.7 ; CN6.7 45.32,7.6 ; CN6.7 47.33,9.61 ; CN6.7 47.33,7.6 ; C31.2 91.01,60.94 ; C31.2 91.01,63.71 ; C31.2 91.51,62.32 ; C31.2 88.25,63.71 ; C31.2 89.63,60.44 ; C31.2 88.25,60.94 ; C31.2 87.75,62.32 ; C31.2 89.63,64.21 ; J4.3 29.47,1.45 ; J4.3 27.61,1.45 ; J4.3 27.61,3.31 ; J4.3 29.47,3.31 ; J8.SH1 7.05,41.98 ; J8.SH1 4.08,44.4 ; J8.SH1 7.05,44.4 ; 2.15,24.61 J9.3 ; TP10.1 60.12,19.61 ; TP10.1 60.12,17.92 ; TP10.1 58.43,17.92 ; TP10.1 58.43,19.61 ; CON2.4 135.12,53.52 ; CON2.4 133.47,54.13 ; CON2.4 133.47,49.61 ; CON2.4 131.82,50.22 ; CON2.4 135.12,50.22 ; CON2.4 135.73,51.87 ; CON2.4 131.21,51.87 ; CON2.4 131.82,53.52 ; C33.2 118.19,63.71 ; C33.2 115.43,60.94 ; C33.2 116.81,64.21 ; C33.2 116.81,60.44 ; C33.2 118.19,60.94 ; C33.2 118.69,62.32 ; C33.2 115.43,63.71 ; C33.2 114.93,62.32 ; 42.78,9.61 CN6.6 ; CN6.6 42.78,7.6 ; CN6.6 44.79,9.61 ; CN6.6 44.79,7.6 ; 75.11,64.91 76.04,63.98 ; 76.04,63.98 75.11,63.04 ; 76.04,63.98 76.97,63.04 ; 76.04,63.98 76.97,64.91 ; J6.5 54.11,64.91 ; J6.5 52.25,64.91 ; J6.5 54.11,63.04 ; J6.5 52.25,63.04 ; 3.15,42.28 J8.SH3 3.15,44.4 ; CON2.3 130.12,53.52 ; CON2.3 126.82,53.52 ; CON2.3 128.47,49.61 ; CON2.3 126.21,51.87 ; CON2.3 128.47,54.13 ; CON2.3 130.73,51.87 ; CON2.3 130.12,50.22 ; CON2.3 126.82,50.22 ; 3.15,36.65 J8.SH4 3.15,34.53 ; 2.15,23.34 J9.5 ; 4.08,34.53 J8.SH2 ; J8.SH2 7.05,34.53 ; J8.SH2 7.05,36.95 ; 2.15,12.41 J3.5 ; CN5.7 30.57,55.86 ; CN5.7 30.57,57.87 ; CN5.7 28.56,55.86 ; CN5.7 28.56,57.87 ; 2.39,9.12 J3.9 ; 2.15,13.68 J3.3 ; 2.39,20.04 J9.9
  PWR w0.835: 102.02,63.53 C32.2 ; C32.2 104.42,63.53 ; C32.2 102.02,61.12 ; C32.2 104.42,61.12 ; 115.61,61.12 C33.2 ; C33.2 118.01,61.12 ; C33.2 115.61,63.53 ; C33.2 118.01,63.53 ; C31.2 90.83,63.53 ; C31.2 88.43,63.53 ; C31.2 88.43,61.12 ; C31.2 90.83,61.12
  BOTTOM w0.305: NET2.2 99.92,8.1 ; NET3.2 86.83,8.22 ; NET1.2 113,8.1
  BOTTOM w0.508: 76.04,63.98 76.04,62.57 R100.1
  BOTTOM w0.835: C32.2 104.42,63.53 ; C32.2 102.02,61.12 ; C32.2 104.42,61.12 ; C32.2 102.02,63.53 ; C31.2 90.83,61.12 ; C31.2 90.83,63.53 ; C31.2 88.43,63.53 ; C31.2 88.43,61.12 ; 115.61,61.12 C33.2 ; C33.2 118.01,63.53 ; C33.2 118.01,61.12 ; C33.2 115.61,63.53
  vias: v1(84.42,65.88) v1(84.42,60.93) v1(96.49,66.01) v1(96.49,60.93) v1(110.08,66.01) v1(110.08,60.93) v1(123.54,64.36) v1(124.43,65.88) v1(124.68,60.93) v2(4.79,55.21) v2(6.19,52.93) v2(6.82,38.19) v2(7.21,55.21) v2(15.08,2.51) v2(15.08,1.49) v2(19.27,42.51) v2(19.27,38.45) v2(41.37,44.04) v2(41.62,46.45) v2(41.75,49.62) v2(42,43.4) v2(43.02,47.59) v2(51.15,36.29) v2(51.15,33.24) v2(54.2,36.29) v2(84.29,5.56) v2(84.29,4.54) v2(85.31,5.56) v2(85.31,4.54) v2(86.33,5.56) v2(86.33,4.54) v2(87.34,5.56) v2(87.34,4.54) v2(88.36,5.56) v2(88.36,4.54) v2(89.37,5.56) v2(89.37,4.54) v2(90.77,3.27) v2(90.77,2.25) v2(91.79,3.27) v2(91.79,2.25) v2(92.8,3.27) v2(92.8,2.25) v2(93.44,43.15) v2(93.44,42.13) v2(93.82,3.27) v2(93.82,2.25) v2(94.84,3.27) v2(94.84,2.25) v2(95.85,3.27) v2(95.85,2.25) v2(97.38,5.56) v2(97.38,4.54) v2(98.39,5.56) v2(98.39,4.54) v2(99.41,5.56) v2(99.41,4.54) v2(100.42,5.56) v2(100.42,4.54) v2(101.44,5.56) v2(101.44,4.54) v2(102.46,5.56) v2(102.46,4.54) v2(103.85,3.27) v2(103.85,2.25) v2(104.87,3.27) v2(104.87,2.25) v2(105.88,3.27) v2(105.88,2.25) v2(106.52,43.15) v2(106.52,42.13) v2(106.9,3.27) v2(106.9,2.25) v2(107.92,3.27) v2(107.92,2.25) v2(108.93,3.27) v2(108.93,2.25) v2(110.46,5.56) v2(110.46,4.54) v2(111.47,5.56) v2(111.47,4.54) v2(112.49,5.56) v2(112.49,4.54) v2(113.5,5.56) v2(113.5,4.54) v2(114.52,5.56) v2(114.52,4.54) v2(115.54,5.56) v2(115.54,4.54) v2(119.6,43.15) v2(119.6,42.13) v2(134.33,9.87) v2(135.48,9.87)
VBAT: length 119.9
  TOP w0.279: v1(46.07,38.07) 46.19,38.07 46.25,38.02 U1.2
  TOP w0.381: v1(37.46,45.69) 43.93,39.21 44.54,39.21 45.27,38.49 C12.1 45.52,38.07 v1(46.07,38.07)
  PWR w0.381: J5.4 41.24,3.65 40.1,4.79 16.48,4.79 1.24,20.03 1.24,28.85 9.56,37.18 9.56,40.66 8.73,41.5 8.73,43.78 10.63,45.69 v1(37.46,45.69)
  BOTTOM w0.508: R7.1 45.67,37.8 45.94,38.07 v1(46.07,38.07)
VCC: length 129.8
  TOP w0.279: 49.42,40.62 U1.63
  TOP w0.635: 46.58,42.64 46.58,43.27 45.81,44.04
  BOTTOM w0.762: R6.2 46.21,43.66 v2(44.8,43.66) v2(43.91,43.66) 42.26,45.31 41.24,45.31 36.03,50.51 21.56,50.51 21.43,50.64 ; 21.43,50.64 19.78,52.29 19.78,57.63 22.83,60.67 R87.2 48.99,60.69 ; 21.43,50.64 21.43,46.83 15.62,41.02 15.62,29.53 19.27,25.88 19.27,13.18 26.89,5.56 30.45,5.56 J5.1
VDD: length 92.2
  TOP w0.381: U2.3 64.05,47.01 64.45,46.61 C41.1
  TOP w0.508: v1(44.45,64.45) SW2.4 ; R79.1 v1(56.1,50.2) 56.1,49.4 D13.1 ; R90.2 v1(35.4,41.75) ; SW1.3 v1(33.88,64.45) SW1.4 ; C41.1 64.45,45.4 v1(63.97,44.93) ; J3.1 3.14,15.46 3.65,15.97 5.05,15.97 12.29,8.73 18.64,8.73 25.62,15.72 v1(25.62,16.73) ; R2.2 59.94,48.55 D12.1 59.15,49.4 v1(59.15,50.2) R78.1 ; SW2.3 v1(45.43,64.45) ; D14.1 53.05,49.4 v1(53.05,50.2) R80.1
  TOP w0.762: CN6.4 C28.1
  PWR w0.581: J2.1 70.94,62.73 ; J2.1 70.94,65.22 ; J2.1 68.44,65.22 ; J2.1 68.44,62.73 ; 37.7,7.6 CN6.4 ; CN6.4 39.71,7.6 ; CN6.4 37.7,9.61 ; CN6.4 39.71,9.61
  BOTTOM w0.508: v1(46.96,29.94) R8.2 ; v1(25.62,16.73) R108.1 ; R65.2 38.7,6.19
  BOTTOM w0.635: R7.2 45.17,39.21 v1(46.19,39.21) v1(46.7,38.7)
  BOTTOM w0.762: v1(44.45,64.45) v1(45.43,64.45) 46.44,64.45 46.73,64.74 R89.2 48.99,64.73
  BOTTOM w1.27: J5.3 CN6.4
  vias: v1(45.69,42.26) v1(45.69,41.5)
VDDA: length 85.9
  TOP w0.279: U1.27 53.92,28.44 54.04,28.31
  TOP w0.381: 54.2,26.89 54.04,27.04 54.04,28.31
  TOP w0.508: C8.2 55.76,24.02 C9.1 55.76,25.33 v2(54.83,26.26) 54.2,26.89 ; D8.1 v2(33.37,30.32)
  TOP w0.762: D9.1 D10.1 D11.1 29.59,31.37 v2(29.56,31.34)
  PWR w0.762: 41.88,23.08 41.88,20.16 43.97,18.07 46.89,18.07 50.77,14.19 50.77,7.71 49.88,6.83 47.21,6.83 43.78,3.4 J5.5 ; 41.88,23.08 33.11,23.08 29.56,26.64 v2(29.56,31.34) 30.57,30.32 v2(33.37,30.32) ; 41.88,23.08 41.88,23.08 43.27,24.48 53.81,24.48 54.83,25.49 v2(54.83,26.26)
  BOTTOM w0.508: v2(54.83,26.26) 54.21,26.88 R9.2 R8.1
BOOT1: length 5.2
  TOP w0.279: 59.91,35.4 59.53,35.02 U1.41
  TOP w0.508: C16.2 60.93,36.42 59.91,35.4
BOOT2: length 4.7
  TOP w0.279: 59.97,33.38 59.84,33.52 U1.38
  TOP w0.508: C17.2 60.11,33.24 59.97,33.38
BOOT3: length 5.4
  TOP w0.279: 58.77,31.59 58.77,31.64
  TOP w0.305: 58.77,31.64 58.39,32.02 U1.35
  TOP w0.508: C18.2 60.29,30.07 58.77,31.59
F103_NRST: length 23.2
  TOP w0.279: U5.7 16.6,18.38 16.1,17.87 16.1,16.01 v1(17.06,15.04) C50.2
  TOP w0.305: R120.1 18.36,15.04 C50.2
  BOTTOM w0.305: J9.10 7.08,18.13 13.97,18.13 v1(17.06,15.04)
F103_SWCLK: length 8.4
  TOP w0.254: U5.37 11.1,26.34 10.89,26.13 6.82,26.13 5.3,24.61 J9.4
F103_SWDIO: length 16.6
  TOP w0.254: v1(7.84,30.96) 10.76,30.96 11.02,31.21 14.32,31.21 14.6,30.93 U5.34
  BOTTOM w0.254: v1(7.84,30.96) 7.84,29.3 J9.2
GHS1: length 14
  TOP w0.305: 58.7,36.16 58.56,36.02 U1.43
  TOP w0.508: D2.1 67.21,43.12 R13.1 63.66,38.32 60.86,38.32 58.7,36.16
GHS2: length 12
  TOP w0.305: U1.40 59.79,34.52 60.04,34.77
  TOP w0.381: 60.04,34.77 60.29,34.77
  TOP w0.508: D3.1 67.21,36.77 R14.1 66.83,35.15 60.67,35.15 60.29,34.77
GHS3: length 12
  TOP w0.305: U1.37 59.31,33.02 59.4,32.92
  TOP w0.508: R15.1 67.21,30.42 D4.1 65.37,30.83 64.23,31.97 60.36,31.97 59.4,32.92
GLS1: length 21.3
  TOP w0.279: U1.29 54.92,28.83 55.03,28.72 55.03,28.21 55.28,27.97
  TOP w0.381: 55.28,27.97 56.1,27.15
  TOP w0.508: 56.1,27.15 60.29,27.15 65.79,21.65 65.79,18.89 D5.1 67.21,17.46 R25.1
GLS2: length 17.8
  TOP w0.279: U1.30 55.42,29.02 55.49,28.95 55.49,28.77 55.59,28.67
  TOP w0.381: 55.59,28.67 55.59,28.54 56.23,27.91
  TOP w0.508: R26.1 67.21,20.77 D6.1 66.8,21.68 60.58,27.91 56.23,27.91
GLS3: length 15.4
  TOP w0.279: 56.35,28.67 55.92,29.1 U1.31
  TOP w0.305: 56.48,28.67 56.35,28.67
  TOP w0.508: 56.48,28.67 60.87,28.67 65.06,24.48 D7.1 67.21,24.07 R27.1
OUT1: length 13.1
  TOP w0.279: 59.15,35.65 59.01,35.52 U1.42
  TOP w0.508: 59.15,35.65 61.13,37.64 63.14,37.64 63.83,36.94 ; 63.83,36.94 63.83,37.42 66.77,40.35 R19.1 ; 63.83,36.94 C16.1
OUT2: length 11.1
  TOP w0.279: 60.24,34.02 U1.39
  TOP w0.508: 63.83,33.76 C17.1 64.6,34 R20.1 ; 63.83,33.76 63.14,34.46 61,34.46 60.56,34.02 60.24,34.02 ; 63.83,33.76 63.83,33.8
OUT3: length 12
  TOP w0.305: U1.36 58.83,32.52 58.99,32.36
  TOP w0.508: C18.1 63.83,30.12 ; 63.83,30.12 63.83,30.59 63.15,31.27 60.08,31.27 58.99,32.36 ; 63.83,30.12 64.75,30.12 R21.1
PA0: length 13.8
  TOP w0.279: 40.9,29.56 C19.2 42.68,29.6 45.6,32.52 U1.13
  TOP w0.508: C19.2 39.24,29.6 R39.2 R37.1 36.45,29.62 D8.2
PA1: length 20.3
  TOP w0.279: U1.14 45.86,32.02 41.88,28.03 R47.2
  TOP w0.305: 34.19,28.23 R44.2 ; 34.19,28.23 34.76,28.8 37.05,28.8 37.62,28.23 ; 34.19,28.23 32.1,30.32 TP4.1 ; 37.62,28.23 38.19,28.8 40.48,28.8 41.05,28.23 R47.2 ; 37.62,28.23 R41.1
PA2: length 18.4
  TOP w0.279: 40.1,27.15 41.75,27.15 46.12,31.52 U1.15
  TOP w0.305: TP7.1 34.89,23.97 v1(35.27,24.35) ; C22.2 39.63,26.68 39.65,26.7 ; 39.65,26.7 39.21,27.15 36.8,27.15 36.23,26.57 R53.1 35.4,26.38 v1(35.27,26.51) ; 39.65,26.7 40.1,27.15
  BOTTOM w0.305: v1(35.27,26.51) v1(35.27,24.35)
PA3: length 44.7
  TOP w0.279: 46.58,31.02 U1.16 ; 45.94,30.57 41.75,26.38 C22.1
  TOP w0.305: v1(61.05,13.81) v1(56.29,18.57) ; 46.58,31.02 46.38,31.02 45.94,30.57 v1(45.94,30.19) ; R50.2 34.38,26.38 35.27,25.49 36.92,25.49 37.62,26.19 R53.2 38.51,25.49 40.48,25.49 41.08,26.09 C22.1
  BOTTOM w0.305: R73.2 v1(61.05,13.81) ; v1(56.29,18.57) 52.67,22.19 47.78,22.19 47.24,22.73 47.24,23.56 45.94,24.86 v1(45.94,30.19)
PA4: length 102.2
  TOP w0.279: J4.1 23.46,7.21 v1(29.81,13.56) 31.46,15.21 32.1,15.21 45.94,29.05 48.61,29.05 48.92,29.37 U1.17
  TOP w0.305: CN5.3 39.72,54.96 v1(34,49.24)
  BOTTOM w0.305: v1(29.81,13.56) 21.56,13.56 20.03,15.08 20.03,27.52 19.34,28.21 19.34,28.22 18.25,29.3 18.25,34.14 33.36,49.24 v1(34,49.24)
PA5: length 103.2
  TOP w0.279: v1(31.72,14.32) 31.84,14.32 46.07,28.54 48.99,28.54 49.42,28.98 U1.18 ; 31.46,14.19 26,8.73 J4.2
  TOP w0.305: v1(31.72,14.32) 31.59,14.32 31.46,14.19 ; v1(34,47.97) 34,48.1 42.26,56.36 CN5.2
  BOTTOM w0.305: v1(31.72,14.32) 21.56,14.32 20.54,15.33 20.54,27.91 18.89,29.56 18.89,33.88 32.99,47.97 v1(34,47.97)
PA6: length 15.9
  TOP w0.279: U1.19 49.92,28.71 48.99,27.78 v1(47.97,27.78)
  TOP w0.3: C23.2 v1(48.1,23.08)
  TOP w0.305: 47.91,20.61 47.78,20.61 47.21,20.03 47.21,19.14 TP8.1 ; 47.91,20.61 47.34,21.18 47.34,22.7 47.72,23.08 v1(48.1,23.08) ; 47.91,20.61 R54.1
  BOTTOM w0.305: v1(48.1,23.08) 48.1,27.65 v1(47.97,27.78)
PA7: length 18.7
  TOP w0.279: R48.2 46,27.02 48.99,27.02 50.42,28.45 U1.20
  TOP w0.305: 43.53,19.53 43.53,21.3 44.23,22 ; 43.53,19.53 43.53,19.27 44.23,18.57 R45.2 ; 43.53,19.53 TP5.1 ; R42.1 44.23,22 ; 44.23,22 43.53,22.7 43.53,24.73 44.23,25.43 R48.2
PA8: length 62.9
  TOP w0.279: U1.44 v1(56.31,36.52)
  BOTTOM w0.305: 48.86,56.86 52.29,60.29 67.91,60.29 69.69,58.51 69.69,55.59 68.42,54.32 62.83,54.32 62.2,53.69 62.2,52.61 63.53,51.28 65.75,51.28 66.77,50.26 66.77,42.26 61.03,36.52 v1(56.31,36.52)
PA9: length 88.1
  TOP w0.279: v1(61.05,39.34) 60.67,39.34 59.66,38.32 59.66,38.02 58.66,37.02 U1.45
  TOP w0.305: v1(61.05,39.34) 61.18,39.34 61.94,40.1 61.94,40.35 68.07,46.48 68.07,57.96 67.77,58.26 65.5,58.26 64.1,56.86
  BOTTOM w0.254: v1(61.05,39.34) 60.8,39.08 54.2,39.08 53.05,37.94 48.99,37.94 47.34,36.29 44.04,36.29 41.75,38.58 41.75,40.61 39.21,43.15 35.76,43.15 25.62,33.01 25.62,22.31 24.62,21.3 R111.1
PA10: length 80
  TOP w0.279: v1(61.05,40.23) 60.75,40.23 59.15,38.62 59.15,38.17 58.49,37.52 U1.46
  TOP w0.305: CN9.1 67.02,56.48 67.02,46.2 v1(61.05,40.23)
  BOTTOM w0.254: v1(61.05,40.23) 60.8,40.23 60.17,39.59 54.07,39.59 52.86,38.39 48.8,38.39 47.21,36.8 44.29,36.8 43.87,37.22 43.87,39.13 39.34,43.66 35.51,43.66 24.99,33.14 24.99,23.7 R109.1
PA11: length 53
  TOP w0.279: U1.47 58.33,38.02 58.64,38.32 58.64,38.96 62.58,42.89 62.96,42.89 65.37,45.31 v1(65.37,47.34) 64.89,47.82 U2.4
  BOTTOM w0.305: 51.4,56.86 54.07,59.53 67.66,59.53 69.05,58.13 69.05,55.72 68.2,54.86 62.48,54.86 61.21,53.6 61.21,50.8 64.68,47.34 v1(65.37,47.34)
PA12: length 45.1
  TOP w0.279: U2.1 62.55,47.82 v1(62.07,47.34) 62.07,43.15 57.5,38.58 U1.48
  BOTTOM w0.305: 53.94,56.86 55.97,58.9 67.4,58.9 68.42,57.88 68.42,55.9 67.89,55.37 62.1,55.37 60.58,53.85 60.58,48.83 v1(62.07,47.34)
PA13: length 94.5
  TOP w0.279: U1.49 56.42,40.04 56.74,40.35 v1(58.26,40.35)
  TOP w0.305: J3.2 4.79,14.95 11.65,8.1 18.89,8.1 26.38,15.59 26.38,25.88 22.19,30.07 v1(22.19,33.88)
  BOTTOM w0.254: R113.1 v1(22.19,33.88) 32.48,44.16 39.46,44.16 43.65,39.97 46.39,39.97 47.53,38.83 52.54,38.83 54.07,40.35 v1(58.26,40.35)
PA14: length 102.5
  TOP w0.279: v1(58.26,41.24) 58.01,40.99 56.35,40.99 55.92,40.56 U1.50
  TOP w0.305: v1(20.03,33.88) 20.79,34.64 22.57,34.64 22.95,34.26 22.95,30.07 26.89,26.13 26.89,15.33 19.14,7.59 10.89,7.59 4.79,13.68 J3.4
  BOTTOM w0.254: v1(58.26,41.24) 57.88,41.24 57.5,40.86 53.94,40.86 52.35,39.27 47.72,39.27 46.51,40.48 43.78,40.48 39.59,44.67 30.83,44.67 v1(20.03,33.88) R112.1
PA15: length 107.7
  TOP w0.279: U1.51 55.42,40.69 56.23,41.5 57.24,41.5 57.88,42.13 v1(58.26,42.13)
  TOP w0.305: v1(13.05,54.07) 19.15,54.07 CN5.10
  BOTTOM w0.305: CN5.10 21.94,56.86 25.37,53.43 42.77,53.43 51.78,44.42 51.78,42.77 52.42,42.13 v1(58.26,42.13) ; 4.41,11.14 4.92,11.14 5.55,11.78 5.55,16.1 2,19.65 2,28.29 13.05,39.34 v1(13.05,54.07)
PB0: length 17
  TOP w0.279: R49.2 50.26,26 51.92,27.67 U1.23
  TOP w0.305: R49.2 50.07,25.43 49.5,24.86 49.5,22.57 50.07,22 ; 50.07,22 R43.1 ; 50.07,22 49.5,21.43 49.5,19.14 50.07,18.57 ; TP6.1 49.12,17.75 49.94,18.57 50.07,18.57 ; R46.2 50.07,18.57
PB1: length 13.4
  TOP w0.279: 51.69,24.01 51.62,24.01 51.15,24.48 51.15,26.13 52.42,27.4 U1.24
  TOP w0.305: C24.2 51.69,24.01 51.15,23.46 51.15,21.3 51.85,20.61 R55.1 53.12,19.53 TP9.1
PB2: length 35.6
  TOP w0.279: U1.25 52.92,27.14 52.04,26.26 C24.1
  TOP w0.305: C24.1 52.33,25.46 52.93,24.86 52.93,22.89 R55.2 53.24,20.8 54.2,20.8 55.21,19.78 ; v1(69.18,13.81) 62.45,13.81 56.48,19.78 55.21,19.78 ; 55.21,19.78 55.21,19.15 54.32,18.26 52.35,18.26 R52.2
  BOTTOM w0.305: R75.2 v1(69.18,13.81)
PB3: length 123.1
  TOP w0.279: U1.54 53.92,41.86 55.72,43.66 v1(55.72,43.91)
  TOP w0.305: v1(17.11,33.88) 18.38,35.15 22.95,35.15 23.59,34.51 23.59,30.19 27.4,26.38 27.4,15.08 19.4,7.08 10.13,7.08 4.79,12.41 J3.6 ; v1(32.1,49.12) CN5.6
  BOTTOM w0.305: v1(55.72,43.91) 55.72,43.66 54.73,42.67 52.77,42.67 52.42,43.02 52.42,44.54 42.89,54.07 34.89,54.07 32.1,56.86 CN5.6 ; v1(32.1,49.12) 17.11,34.13 v1(17.11,33.88) R115.1
PB4: length 32
  TOP w0.279: v1(54.83,43.91) 54.83,43.78 53.42,42.37 U1.55
  BOTTOM w0.305: v1(54.83,43.91) 54.83,43.66 54.39,43.22 53.24,43.22 53.02,43.43 53.02,44.77 43.09,54.7 36.8,54.7 34.64,56.86 CN5.5
PB5: length 27.3
  TOP w0.279: U1.56 52.92,42.89 v1(53.94,43.91)
  BOTTOM w0.305: v1(53.94,43.91) 53.94,44.67 43.27,55.34 38.71,55.34 CN5.4
PB6: length 15.3
  TOP w0.279: U1.57 52.42,43.53 53.56,44.67 56.27,44.67 C34.1
  TOP w0.305: C34.1 57.66,47.82 R85.2 57.69,49.34 D12.2 57.66,51.05 R81.2
PB7: length 12.9
  TOP w0.279: C35.1 53.73,45.18 53.31,45.18 51.92,43.8 U1.58
  TOP w0.305: R82.2 54.61,51.05 D13.2 54.64,49.34 R86.2 54.61,47.82 C35.1
PB8: length 11.6
  TOP w0.279: C36.1 51.42,45.93 U1.59
  TOP w0.305: C36.1 51.57,47.09 51.59,47.12 R88.2 51.59,48.59 51.56,48.62 D14.2 51.56,50.26 51.53,50.29 R83.2
PB9: length 43.8
  TOP w0.279: v1(46.83,58.64) 46.83,56.1 50.39,52.55 50.39,45.81 50.92,45.28 U1.60
  BOTTOM w0.305: CN5.9 26.26,58.64 v1(46.83,58.64)
PB10: length 58.3
  TOP w0.279: U1.28 54.42,28.67 54.58,28.52 54.58,27.78 54.7,27.65
  TOP w0.305: v1(62.96,58.13) 63.88,59.05 67.95,59.05 68.93,58.07 v1(68.93,52.42) ; 59.07,25.74 v1(60.16,25.74) ; 59.07,25.74 58.64,25.74 58.12,26.26 56.1,26.26 54.7,27.65 ; 59.07,25.74 R96.2
  BOTTOM w0.305: v1(68.93,52.42) 68.93,30.7 63.96,25.74 v1(60.16,25.74) ; CN9.4 60.29,58.13 v1(62.96,58.13)
PC0: length 55.1
  TOP w0.279: C25.2 41.08,35.82 v1(42.07,34.83) 42.38,34.52 U1.9
  TOP w0.305: 37.62,36.35 38.32,37.05 40.48,37.05 41.08,36.45 C25.2 ; 37.62,36.35 R57.2 ; 37.62,36.35 36.92,37.05 35.15,37.05 34.45,36.35 ; 34.45,36.35 33.75,37.05 31.72,37.05 31.05,36.39 D9.2 ; 34.45,36.35 R62.2
  BOTTOM w0.305: R70.2 55.73,15.59 48.86,15.59 45.31,19.14 45.31,20.16 44.92,20.54 44.16,20.54 41.11,23.59 41.11,34 41.94,34.83 v1(42.07,34.83)
PC1: length 57.4
  TOP w0.279: 41.74,34.02 U1.10
  TOP w0.305: R63.2 34.45,34.58 ; 34.45,34.58 33.75,35.27 31.72,35.27 31.05,34.61 D10.2 ; 34.45,34.58 35.15,35.27 36.92,35.27 37.62,34.58 ; v1(42,33.75) 41.37,34.38 ; 37.62,34.58 R59.2 ; 37.62,34.58 38.32,35.27 40.48,35.27 41.37,34.38 ; 41.37,34.38 C26.2
  BOTTOM w0.305: R71.2 63.09,13.18 60.04,16.22 50.26,16.22 47.21,19.27 47.21,20.41 46.58,21.05 44.42,21.05 41.75,23.72 41.75,33.5 v1(42,33.75)
PC2: length 58.7
  TOP w0.279: U1.11 44.78,33.52 43.87,32.61 v1(42.51,32.61)
  TOP w0.305: D11.2 31.05,32.83 31.72,33.5 33.75,33.5 34.45,32.8 ; 34.45,32.8 35.15,33.5 36.92,33.5 37.62,32.8 ; 34.45,32.8 R64.2 ; 37.62,32.8 38.32,33.5 40.48,33.5 41.37,32.61 ; 37.62,32.8 R61.2 ; v1(42.51,32.61) 41.37,32.61 ; 41.37,32.61 C27.2
  BOTTOM w0.305: R72.2 67.15,13.18 62.83,17.49 55.34,17.49 51.27,21.56 44.67,21.56 42.38,23.84 42.38,32.48 v1(42.51,32.61)
PC3: length 97.5
  TOP w0.279: v1(30.83,31.46) 31.21,31.84 44.16,31.84 45.33,33.02 U1.12
  TOP w0.305: v1(29.56,24.99) 24.22,30.32 24.22,34.77 22.95,36.04 v1(14.57,36.04)
  BOTTOM w0.305: v1(30.83,31.46) 29.56,30.19 v1(29.56,24.99) 29.56,22.95 40.73,11.78 52.86,11.78 53.38,12.3 R67.2 ; v1(14.57,36.04) 14.57,53.69 15.22,54.34 R38.1
PC4: length 65.6
  TOP w0.279: U1.21 50.92,28.19 49.12,26.38 v1(48.86,26.38) 47.12,26.38 C20.2
  TOP w0.305: R40.2 45.31,22.89 45.31,24.86 45.9,25.46 C20.2
  PWR w0.305: v1(74.13,16.48) 74.52,16.86 76.04,16.86 83.15,9.75 90.77,9.75 92.17,11.14 v1(92.55,11.14)
  BOTTOM w0.305: NTC1.2 93.63,10.19 92.68,11.14 v1(92.55,11.14) ; v1(74.13,16.48) 73.5,17.11 66.39,17.11 62.96,20.54 58.13,20.54 53.18,25.49 49.75,25.49 v1(48.86,26.38)
PC5: length 35.4
  TOP w0.279: U1.22 51.42,27.93 48.95,25.46 48.39,25.46 ; C23.1 48.1,25.49
  TOP w0.305: 48.29,22 48.99,21.3 48.99,20.03 48.48,19.53 v1(48.1,19.53) R51.2 ; 48.29,22 48.99,22.7 48.99,24.86 48.39,25.46 C23.1 ; 48.29,22 R54.2
  BOTTOM w0.305: v1(48.1,19.53) 50.77,16.86 61.43,16.86 65.12,13.18 R74.2
PC13: length 16.9
  TOP w0.279: R91.2 39.11,43.27 41.88,40.51 41.88,38.83 43.4,37.31 46.58,37.31 46.79,37.52 U1.3
PC14: length 39
  TOP w0.279: v1(49.5,36.8) 49.46,36.8 49.24,37.02 U1.4
  TOP w0.305: CN9.3 61.82,56.86 65.24,53.43 65.24,50.96 ; 65.24,50.96 65.24,50.72 64.94,50.41 U2.5 64.72,50.39 v1(65.37,50.39) ; 65.24,50.96 65.37,51.09 R99.2
  BOTTOM w0.254: v1(49.5,36.8) 49.75,37.05 53.43,37.05 53.94,37.56 61.31,37.56 66.13,42.38 66.13,49.62 v1(65.37,50.39)
PC15: length 37.5
  TOP w0.279: U1.5 48.76,36.52 v1(49.37,35.91)
  BOTTOM w0.254: 56.48,56.86 57.62,55.72 57.62,45.81 61.98,41.46 61.98,38.99 61.05,38.07 53.81,38.07 53.24,37.5 49.18,37.5 48.73,37.05 48.73,36.29 49.12,35.91 v1(49.37,35.91)
PD2: length 23
  TOP w0.279: U1.53 54.42,41.34 v1(56.23,43.15)
  BOTTOM w0.305: CN5.1 44.8,56.61 56.48,44.93 56.48,43.4 v1(56.23,43.15)
PF0: length 14.5
  TOP w0.254: U1.6 44.06,36.02 41.37,38.7 41.37,39.97 40.86,40.48 v1(40.61,40.48)
  TOP w0.305: X1.1 39.21,41.62 ; 39.21,41.62 39.21,42.15 C4.1 ; 39.21,41.62 39.97,41.62 40.61,40.99 v1(40.61,40.48)
  BOTTOM w0.305: R68.2 v1(40.61,40.48)
PF1: length 14.1
  TOP w0.254: U1.7 43.92,35.52 41.11,38.32 v1(40.61,38.32)
  TOP w0.305: X1.3 37.94,38.81 C5.2 38.04,38.37 38.35,38.07 40.35,38.07 v1(40.61,38.32)
  BOTTOM w0.305: v1(40.61,38.32) 40.36,38.56 39.47,38.56 R69.2
PG10: length 89
  TOP w0.279: U1.8 43.66,35.02 41.11,37.56 35.08,37.56 34.45,38.19 R92.2
  TOP w0.305: 34.48,38.16 34,37.69 32.1,37.69 v1(31.97,37.81) ; v1(28.16,19.02) 28.03,18.89 28.03,14.95 19.65,6.57 7.71,6.57 J3.10
  BOTTOM w0.254: R118.1 v1(28.16,19.02) 28.34,19.02
  BOTTOM w0.305: CN6.3 36.16,12.54 29.68,19.02 28.34,19.02 28.03,19.32 28.03,33.88 v1(31.97,37.81)
SCREF: length 34
  TOP w0.279: 57.66,43.41 57.66,43.31 56.35,42 55.97,42 54.92,40.95 U1.52
  TOP w0.305: J2.2 66.39,63.98 60.29,57.88 60.29,51.02 61.43,49.88 61.43,47.72 60.86,47.15 R2.1 61.43,46.39 61.43,44.93 60.86,44.35 R3.2 59.73,43.41 57.66,43.41 C3.2
STLINK_LED: length 30.8
  TOP w0.305: 4.16,47.21 R122.1 ; 4.16,47.21 R121.1 ; 4.16,47.21 4.16,46.45 4.41,46.2 10.51,46.2 13.56,43.15 13.56,35.27 17.87,30.96 17.87,30.19 16.6,28.92 16.6,27.84 U5.30
STLINK_NRST: length 6.3
  TOP w0.305: U5.18 v1(21.81,23.34)
  BOTTOM w0.305: v1(21.81,23.34) 21.68,23.21 21.68,20.66 R118.2
STLINK_SWCLK: length 4.3
  TOP w0.279: U5.26 18.6,29.01 20.03,30.45 v1(20.03,30.57)
  BOTTOM w0.305: R112.2 v1(20.03,30.57)
STLINK_SWDIO: length 6.4
  TOP w0.279: U5.25 19.1,28.29 21.3,30.49
  TOP w0.305: 21.3,30.49 v1(21.3,30.57) 21.3,30.64 R114.2
  BOTTOM w0.305: v1(21.3,30.57) 22.19,31.46 R113.2
STLINK_SWO: length 4.2
  TOP w0.305: v1(17.11,30.57) 16.1,29.56 U5.31
  BOTTOM w0.305: R115.2 v1(17.11,30.57)
STLINK_UART_RX: length 2.9
  TOP w0.305: v1(22.45,21.18) 22.11,20.84 U5.13
  BOTTOM w0.305: v1(22.45,21.18) R111.2
STLINK_UART_TX: length 9.4
  TOP w0.305: v1(21.3,19.34) U5.12
  BOTTOM w0.305: R109.2 22.56,24.1 21.48,24.1 21.05,23.67 21.05,19.59 v1(21.3,19.34)
SW: length 11.6
  TOP w0.279: U1.62 49.92,40.94 49.88,40.99
  TOP w0.457: 49.88,40.99 49.12,41.75
  TOP w0.635: L1.1 47.44,45.73 47.44,43.05 48.73,41.75 49.12,41.75
  TOP w0.762: 47.73,46.02 L1.1
  TOP w1.016: D1.1 47.73,49.24 47.73,46.02
U: length 89.2
  TOP w0.454: 127.27,24.5 CON1.1 ; CON1.1 129.67,26.9 ; CON1.1 127.27,26.9 ; CON1.1 129.67,24.5 ; 132.27,26.9 CON1.2 ; CON1.2 132.27,24.5 ; CON1.2 134.67,24.5 ; CON1.2 134.67,26.9
  TOP w0.508: v1(80.52,39.97) 79.21,39.97 78.83,40.35 R19.2 R56.1
  PWR w0.508: v1(80.52,39.97) 81.53,40.99 114.39,40.99 v1(115.16,40.23)
  BOTTOM w0.581: CON1.1 130.09,25.7 ; CON1.1 128.47,27.33 ; CON1.1 129.67,24.5 ; CON1.1 127.27,26.9 ; CON1.1 129.67,26.9 ; CON1.1 127.27,24.5 ; CON1.1 128.47,24.08 ; CON1.1 126.84,25.7 ; 132.27,24.5 CON1.2 ; CON1.2 133.47,27.33 ; CON1.2 135.09,25.7 ; CON1.2 131.84,25.7 ; CON1.2 132.27,26.9 ; CON1.2 133.47,24.08 ; CON1.2 134.67,26.9 ; CON1.2 134.67,24.5
  vias: v1(109.95,24.35) v1(109.95,23.59) v1(110.84,24.73) v1(110.84,23.72) v1(110.84,22.7) v1(112.49,24.73) v1(112.49,23.72) v1(112.49,22.7) v1(114.14,24.73) v1(114.14,23.72) v1(114.14,22.7) v1(115.03,24.35) v1(115.03,23.59)
